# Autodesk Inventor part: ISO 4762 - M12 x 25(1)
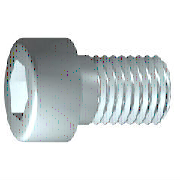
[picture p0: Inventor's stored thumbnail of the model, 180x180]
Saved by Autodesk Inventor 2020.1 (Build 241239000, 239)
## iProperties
Created: 2019-01
Part Number: ISO 4762 - M12 x 25(1)
Material: Edelstahl, 440C
Description: Innensechskantschraube
Document SubType Name: Modeling
Standard: ISO 4762
Designer: lutzd
Standard Revision: Fourth edition 2004-03-01
Standards Organization: ISO
Language: de-DE
Size Designation: M12 x 25
Categories: <MemberInstance><Categories><Category DisplayName="Verbindungselemente" InternalName="e4da775c-781d-43d5-af7c-5136215cf5a6" Mnemonic="FSTN"><Category DisplayNam
Mass: 40.3851 g
Surface Area: 23.0482 cm^2
Volume: 5.21098 cm^3
Density: 7.75 g/cm^3
Appearance: Halbpoliert
IsCustomPart: 0
Author: lutzd
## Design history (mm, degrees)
body "Solid1"
sketch "Skizze1"
  geometry: L1 (-2.667, 0)-(25, 0); L2 (25, 0)-(25, 6); L3 (25, 6)-(4.375, 6); L4 (4.375, 6)-(3.301, 6); L5 (3.301, 6)-(0, 6); L6 (0, 6)-(0, 9); L7 (0, 9)-(-12, 9); L8 (-12, 9)-(-12, 5.774); L9 (-12, 5.774)-(-6, 5.774); L10 (-6, 5.774)-(-2.667, 0); L11 (-19.4, 0)-(32.4, 0) reference; L12 (0, -1.8)-(0, 10.8) reference; L13 (4.375, 6)-(0, 6)
  constraints: 22 end point, 6 parallel, 2 collinear, 2 perpendicular, 1 horizontal, 1 point on line
  dimensions: "d1" = 20.625 distance from line of L3.end L2 (= GEL); "d2" = 1.07364 distance of L4.end L3.end (computed from GAL); "d3" = 12 distance between parallel lines of L8 L6 (= KOH); "d4" = 6 distance of L8.end L9.end (= INTI); "d5" = 60 deg angle of L10 L1; "d6" = 12 diameter of L3 L1 (= GD); "d7" = 12 diameter of L5 L1 (= BDM); "d8" = 11.54701 diameter of L9 L1 (= 1.1547 x SW); "d9" = 18 diameter of L7 L1 (= KOD); "d26" = 25 distance between parallel lines of L12 L2 (= NLG)
workplane "Work Plane1"
fillet "Fillet2" dims "d30" = 0.1 (= R)
revolve "Körper" stored, may be unused: angle "d10" = 90 deg
sketch "Skizze2"
  geometry: L1 (0, -12.6)-(0, 12.6) reference; L2 (-12.6, 0)-(12.6, 0) reference; L3 (5.774, 0)-(2.887, -5); L4 (2.887, -5)-(-2.887, -5); L5 (-2.887, -5)-(-5.774, 0); L6 (-5.774, 0)-(-2.887, 5); L7 (-2.887, 5)-(2.887, 5); L8 (2.887, 5)-(5.774, 0); 2 further points
  constraints: 12 end point, 1 coincident, 1 horizontal alignment, 1 point on line, 12 other
extrude "Loch" join sketch "Skizze2" stored distance "d11" = 10; taper "d12" = 0 deg
fillet "Rundung1" dims "d17" = 1.2 (= RR)
feature "Gewinde" dims "d13" = 20.625 (= GEL), "d14" = 0
chamfer "Fase1" distance "d15" = 1.07354 (= -0.5 x SPD + 0.5 x GD); stored, may be unused: second distance "d16" = 1.07354 (= GUL), angle "d27" = 45 deg
other parameters: "GD" = 12 [user parameter; used in 2 equation terms], "NLG" = 25 [user parameter; used in 1 equation term], "GEL" = 20.625 [user parameter; used in 2 equation terms], "KOD" = 18 [user parameter; used in 1 equation term], "KOH" = 12 [user parameter; used in 1 equation term], "INTI" = 6 [user parameter; used in 1 equation term], "GAL" = 1.07354 (= 0.61345 x PTC) [user parameter; used in 1 equation term], "GUL" = 1.07354 (= 0.61345 x PTC) [user parameter; used in 1 equation term], "BDM" = 12 (= NND) [user parameter; used in 1 equation term], "RR" = 1.2 [user parameter; used in 1 equation term], "SPD" = 9.85293 (= NND - 1.2269 x PTC) [user parameter; used in 1 equation term], "d19" = 0, "d28" = 0, "d29" = 0, "R" = 0.1 [user parameter; used in 1 equation term], "TOA" = 30 deg [user parameter], "GD1" = 9.85293 (= THREADDIA - 1.2269 x PTC) [user parameter], "THREADDIA" = 12 [user parameter; used in 1 equation term], "FAWI" = 45 deg [user parameter], "TPU" = 5.71429 (computed from PTC) [user parameter], "PTC" = 1.75 [user parameter; used in 5 equation terms], "NND" = 12 [user parameter; used in 2 equation terms], "E0" = 11.55 (= 1.155 x SW) [user parameter]
